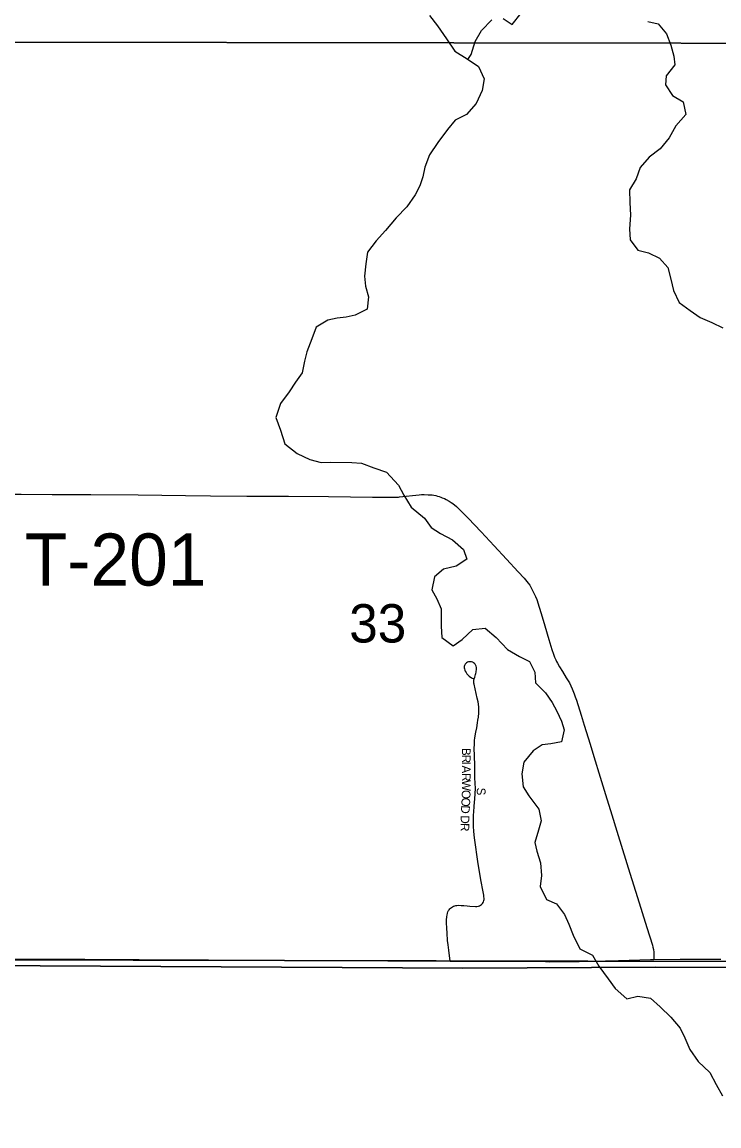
# Model space of a CAD drawing. Extents: x 0 to 34, y 0 to 22.
# Drawn here: x 6.505 to 6.886, y 17.325 to 17.927 of the extents above; entities that cross this region are included whole.
import ezdxf

# ---------------------------------------------------------------- set-up
doc = ezdxf.new("R2010")
doc.units = 0
for name, color, linetype in [('GM_X_Minor_River', 7, 'Continuous'), ('GM_X_Section', 7, 'Continuous'), ('GM_X_Section_Text', 7, 'Continuous'), ('GM_X_Township', 7, 'Continuous'), ('GM_X_Township_Road', 7, 'Continuous'), ('GM_X_Township_Road_Text', 7, 'Continuous'), ('GM_X_Township_Subdivision', 7, 'Continuous'), ('GM_X_Township_Subdivision_Text', 7, 'Continuous'), ('GM_X_US_Route', 7, 'Continuous')]:
    doc.layers.add(name, color=color, linetype=linetype)

msp = doc.modelspace()

# ---------------------------------------------------------------- linework, layer by layer
at = {"layer": 'GM_X_Minor_River'}
for points in [[(6.72763, 17.93078), (6.73195, 17.92505), (6.73683, 17.91799), (6.74152, 17.91132), (6.74813, 17.90709), (6.75437, 17.90287), (6.75754, 17.89621), (6.75636, 17.88976), (6.75308, 17.88277), (6.74791, 17.87674), (6.74163, 17.87356), (6.73742, 17.86847), (6.73224, 17.86148), (6.72764, 17.85469), (6.72513, 17.84807), (6.72395, 17.84276), (6.7224, 17.83784), (6.71989, 17.83293), (6.71529, 17.82632), (6.70937, 17.82029), (6.70363, 17.81351), (6.69846, 17.80785), (6.69386, 17.80163), (6.69287, 17.79518), (6.69225, 17.78855), (6.69278, 17.78304), (6.69444, 17.77715), (6.69364, 17.77051), (6.68716, 17.76714), (6.68222, 17.76604), (6.67728, 17.76551), (6.67215, 17.76441), (6.66586, 17.76066), (6.66335, 17.75423), (6.66064, 17.74723), (6.65947, 17.74212), (6.65809, 17.73568), (6.65445, 17.73058), (6.651, 17.7253), (6.6464, 17.71907), (6.64387, 17.71131), (6.64629, 17.70446), (6.6487, 17.69704), (6.65549, 17.69168), (6.6623, 17.6884), (6.66855, 17.68684), (6.67386, 17.68699), (6.68525, 17.6869), (6.69056, 17.68648), (6.69718, 17.68397), (6.70418, 17.68145), (6.71077, 17.67438)], [(6.74857, 17.9068), (6.75043, 17.90954), (6.75257, 17.91655), (6.75603, 17.92259), (6.76157, 17.92843)], [(6.76784, 17.92914), (6.77275, 17.92588), (6.77773, 17.93211)], [(6.84675, 17.92741), (6.85244, 17.92623), (6.85695, 17.92069), (6.85937, 17.9146), (6.86104, 17.90852), (6.86157, 17.90377), (6.85678, 17.89774), (6.85637, 17.893), (6.86031, 17.88709), (6.86598, 17.88363), (6.86745, 17.87679), (6.86209, 17.87056), (6.85843, 17.86395), (6.85346, 17.85792), (6.84754, 17.85341), (6.84257, 17.84775), (6.84044, 17.8417), (6.83679, 17.83565), (6.83693, 17.82863), (6.83726, 17.8218), (6.83682, 17.8144), (6.83716, 17.80833), (6.84129, 17.8026), (6.84716, 17.80123), (6.85321, 17.79834), (6.85773, 17.79318), (6.85939, 17.78691), (6.86086, 17.78064), (6.86385, 17.77416), (6.86989, 17.76975), (6.87537, 17.76592), (6.88161, 17.76321), (6.88766, 17.76032)], [(6.71077, 17.67438), (6.71358, 17.66904), (6.7177, 17.66237), (6.72487, 17.65643), (6.72863, 17.65128), (6.73373, 17.64802), (6.74015, 17.64456), (6.74619, 17.63939), (6.74804, 17.63406), (6.74214, 17.63031), (6.73529, 17.62865), (6.73033, 17.62433), (6.72895, 17.61732), (6.73157, 17.61237), (6.734, 17.60704), (6.73393, 17.59755), (6.73445, 17.59128), (6.74049, 17.58668), (6.74545, 17.59025), (6.75137, 17.59571), (6.75801, 17.59642), (6.76405, 17.59125), (6.77026, 17.58475), (6.77669, 17.58091), (6.78217, 17.57821), (6.78516, 17.57231), (6.7855, 17.56661), (6.79096, 17.56107), (6.79453, 17.55592), (6.79715, 17.55116), (6.79958, 17.54564), (6.80106, 17.54088), (6.79968, 17.53444), (6.79379, 17.53335), (6.78905, 17.53281), (6.78428, 17.52944), (6.77911, 17.52321), (6.77793, 17.51696), (6.77882, 17.50974), (6.78182, 17.50498), (6.78727, 17.49754), (6.78855, 17.49127), (6.78719, 17.48616), (6.78505, 17.47953), (6.78616, 17.47478), (6.7882, 17.46831), (6.78871, 17.46148), (6.7881, 17.45541), (6.79146, 17.44837), (6.79695, 17.44605), (6.80127, 17.44014), (6.8037, 17.43481), (6.80612, 17.42891), (6.80967, 17.42148), (6.81667, 17.41801), (6.82004, 17.41192), (6.82511, 17.40505), (6.82886, 17.39971), (6.83528, 17.39416), (6.84136, 17.39563), (6.84818, 17.39444), (6.85346, 17.38985), (6.8593, 17.38411), (6.86438, 17.37819), (6.86699, 17.37286), (6.8696, 17.36639), (6.8743, 17.3599), (6.88052, 17.35397), (6.88407, 17.34731), (6.88744, 17.34121)]]:
    msp.add_lwpolyline(points, dxfattribs=at)
at = {"layer": 'GM_X_Section'}
for points in [[(6.99984, 18.41775), (6.98884, 17.91553), (6.4928, 17.91626), (6.50305, 18.41943)], [(6.98884, 17.91553), (6.97935, 17.41426), (6.48295, 17.41537), (6.4928, 17.91626)], [(6.47745, 17.41541), (6.48295, 17.41537), (6.97935, 17.41426), (6.97584, 16.9012), (6.47069, 16.89897)]]:
    msp.add_lwpolyline(points, close=True, dxfattribs=at)
at = {"layer": 'GM_X_Township'}
for points in [[(6.97838, 17.41123), (6.85112, 17.41144), (6.74587, 17.41079), (6.41604, 17.41268), (6.21985, 17.41235), (5.85482, 17.41232), (5.46352, 17.41199), (5.46485, 17.53523), (5.46518, 17.63837), (5.46592, 17.82417), (5.46606, 17.86097), (5.46575, 18.22108), (5.4678, 18.39922), (5.46813, 18.42722), (5.46918, 18.51868), (5.46955, 18.55069), (5.47024, 18.61055), (5.47055, 18.63752), (5.47095, 18.67198), (5.47122, 18.69589), (5.47192, 18.75628), (5.47212, 18.77357), (5.47293, 18.84412), (5.47565, 19.08008)], [(5.45812, 16.85635), (5.46352, 17.41199), (5.85482, 17.41232), (6.21985, 17.41235), (6.41604, 17.41268), (6.74587, 17.41079), (6.85112, 17.41144), (6.97838, 17.41123), (7.4791, 17.40579), (7.48595, 17.40578), (7.97617, 17.40455), (7.9915, 17.4046), (8.4927, 17.4064), (8.48897, 16.91291)]]:
    msp.add_lwpolyline(points, dxfattribs=at)
at = {"layer": 'GM_X_Township_Road'}
for points in [[(6.36818, 17.66874), (6.38374, 17.66895), (6.39928, 17.66904), (6.4152, 17.66915), (6.43382, 17.66929), (6.45362, 17.66951), (6.47653, 17.66956), (6.50486, 17.66946), (6.52181, 17.66939), (6.53767, 17.66933)], [(6.53767, 17.66933), (6.5429, 17.66931), (6.56869, 17.66908), (6.59447, 17.66881), (6.60815, 17.66869), (6.62803, 17.66853), (6.65072, 17.66842), (6.67256, 17.6682), (6.69655, 17.66792), (6.70872, 17.66788), (6.71012, 17.66793), (6.71067, 17.66796)], [(6.71067, 17.66796), (6.71131, 17.66801), (6.72196, 17.66925), (6.72332, 17.66933), (6.72464, 17.66933), (6.72694, 17.66925), (6.72805, 17.66916), (6.72912, 17.66908), (6.72994, 17.66896), (6.73105, 17.66875), (6.73208, 17.66851), (6.7329, 17.66826), (6.73385, 17.66793), (6.73463, 17.6676), (6.73574, 17.66711), (6.73681, 17.66658), (6.73845, 17.66567), (6.7394, 17.66505), (6.74034, 17.66436), (6.74232, 17.6628), (6.74499, 17.66033), (6.74865, 17.65646), (6.75577, 17.6489), (6.76284, 17.64138), (6.76963, 17.6341), (6.77604, 17.62723), (6.77925, 17.62366), (6.78143, 17.62099), (6.7823, 17.61979), (6.78316, 17.6184), (6.7839, 17.61704), (6.78481, 17.61523), (6.7855, 17.61367), (6.78616, 17.61202), (6.78756, 17.60795), (6.78863, 17.60442), (6.79061, 17.59776), (6.79279, 17.59019), (6.79439, 17.58476), (6.79526, 17.58217), (6.79588, 17.58061), (6.79652, 17.5791), (6.79694, 17.57823), (6.79744, 17.57728), (6.79859, 17.57539), (6.80023, 17.57267), (6.80229, 17.56939), (6.80394, 17.56651), (6.80472, 17.56495), (6.8055, 17.56326), (6.80661, 17.56051), (6.80719, 17.55899), (6.80785, 17.55717), (6.8104, 17.54899), (6.81209, 17.54344), (6.8153, 17.53304), (6.81739, 17.5263), (6.82073, 17.51515), (6.82365, 17.5057), (6.82706, 17.4946), (6.82986, 17.48559), (6.83295, 17.47556), (6.83698, 17.46273), (6.8411, 17.44937), (6.84629, 17.43305), (6.84924, 17.42347), (6.84957, 17.42236), (6.84986, 17.42112), (6.85003, 17.41952), (6.85007, 17.41767), (6.85011, 17.41562)]]:
    msp.add_lwpolyline(points, dxfattribs=at)
at = {"layer": 'GM_X_Township_Subdivision'}
msp.add_lwpolyline([(6.73891, 17.41466), (6.7381, 17.42073), (6.73783, 17.42352), (6.73752, 17.42598), (6.73721, 17.42999), (6.73706, 17.43271), (6.73694, 17.43557), (6.73691, 17.43701), (6.73707, 17.439), (6.7372, 17.43983), (6.73742, 17.44083), (6.73769, 17.44153), (6.73804, 17.44224), (6.73841, 17.44277), (6.73878, 17.44323), (6.73918, 17.44361), (6.73971, 17.44403), (6.7402, 17.44433), (6.74079, 17.44463), (6.74139, 17.44485), (6.74197, 17.44501), (6.74263, 17.44511), (6.74351, 17.44519), (6.74489, 17.44514), (6.74631, 17.44505), (6.74815, 17.44489), (6.74964, 17.44474), (6.75274, 17.44447), (6.75353, 17.4445), (6.75429, 17.44463), (6.75486, 17.44483), (6.75554, 17.44518), (6.7561, 17.44561), (6.75661, 17.44615), (6.75698, 17.44666), (6.75718, 17.44709), (6.75733, 17.44775), (6.75741, 17.4483), (6.75741, 17.44898), (6.75733, 17.44979), (6.7572, 17.45064), (6.75685, 17.45253), (6.75564, 17.45912), (6.75395, 17.46915), (6.75235, 17.48067), (6.7521, 17.48338), (6.75188, 17.48578), (6.75172, 17.4879), (6.7516, 17.49024), (6.7516, 17.49267), (6.7517, 17.49453), (6.7518, 17.49596), (6.75209, 17.49921), (6.75246, 17.5032), (6.75267, 17.50883), (6.75241, 17.51467), (6.7523, 17.52117), (6.75216, 17.52709), (6.75207, 17.53054), (6.75212, 17.53321), (6.75223, 17.53519), (6.75241, 17.53655), (6.75299, 17.53967), (6.7534, 17.5421), (6.75385, 17.54471), (6.75409, 17.54625), (6.7543, 17.54785), (6.7545, 17.55024), (6.75463, 17.55192), (6.75459, 17.55336), (6.75438, 17.55489), (6.75413, 17.55615), (6.75369, 17.55818), (6.75314, 17.56071), (6.75199, 17.56586), (6.75187, 17.56646), (6.75181, 17.56695), (6.75181, 17.56757), (6.75191, 17.56819), (6.75207, 17.56884), (6.7523, 17.56958), (6.75253, 17.57039), (6.75273, 17.57111), (6.75294, 17.57174), (6.75308, 17.57244), (6.75318, 17.573), (6.75326, 17.5737), (6.75329, 17.57436), (6.75322, 17.57495), (6.75312, 17.57558), (6.75298, 17.5761), (6.75259, 17.57676), (6.7522, 17.57719), (6.75172, 17.57756), (6.75129, 17.57781), (6.75063, 17.57801), (6.7501, 17.5781), (6.74948, 17.5781), (6.74887, 17.57797), (6.74829, 17.57777), (6.7478, 17.5775), (6.74739, 17.57713), (6.7471, 17.57678), (6.74685, 17.57637), (6.74672, 17.57601), (6.74656, 17.57541), (6.74656, 17.57482), (6.74667, 17.57419), (6.74687, 17.57355), (6.74716, 17.57291), (6.74759, 17.57219), (6.74805, 17.57154), (6.74852, 17.57096), (6.74887, 17.57059), (6.74932, 17.57018), (6.74994, 17.56971), (6.75035, 17.56944), (6.75099, 17.56914), (6.75177, 17.56888)], dxfattribs=at)
at = {"layer": 'GM_X_US_Route'}
for points in [[(6.46094, 17.41556), (6.47686, 17.41578), (6.51384, 17.41581), (6.53963, 17.41577), (6.56915, 17.41564), (6.60705, 17.4154), (6.62383, 17.41529), (6.67075, 17.41513), (6.73891, 17.41466), (6.76647, 17.41461), (6.79101, 17.41442)], [(6.79101, 17.41442), (6.79288, 17.4144), (6.80934, 17.41457), (6.83077, 17.41513), (6.84817, 17.41559), (6.85011, 17.41562), (6.86433, 17.41583), (6.88236, 17.41575), (6.88666, 17.41571)]]:
    msp.add_lwpolyline(points, dxfattribs=at)

# ---------------------------------------------------------------- texts
at = {"layer": 'GM_X_Section_Text'}
msp.add_text('33', height=0.020928, rotation=0.00001, dxfattribs=at).set_placement((6.68382, 17.58858))
at = {"layer": 'GM_X_Township_Road_Text'}
msp.add_text('T-201', height=0.028409, rotation=0.00001, dxfattribs=at).set_placement((6.50674, 17.61966))
at = {"layer": 'GM_X_Township_Subdivision_Text'}
for s, rotation, p in [('B', 270, (6.74532, 17.53105)), ('R', 269.99405, (6.74532, 17.5273)), ('I', 270, (6.74532, 17.52355)), ('A', 269.99284, (6.74532, 17.52147)), ('W', 269.93274, (6.74532, 17.51355)), ('R', 269.99405, (6.74532, 17.5173)), ('O', 268.84155, (6.74531, 17.50816)), ('S', 270, (6.75347, 17.50938)), ('O', 266.56679, (6.74523, 17.50404)), ('D', 268.29262, (6.74475, 17.49431)), ('D', 267.38073, (6.74498, 17.49981)), ('R', 269.57836, (6.74462, 17.49003))]:
    msp.add_text(s, height=0.00473, rotation=rotation, dxfattribs=at).set_placement(p)

doc.saveas('drawing.dxf')
